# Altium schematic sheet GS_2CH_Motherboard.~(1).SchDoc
size A1; Dpartment: R&D; Date: 2024-10-27; DrawnBy: 杜龙彬; DocumentNumber: 2; Revision: V1.01; SheetNumber: 2; SheetTotal: 2; Model: 型号; Size: A1; Department: R&D
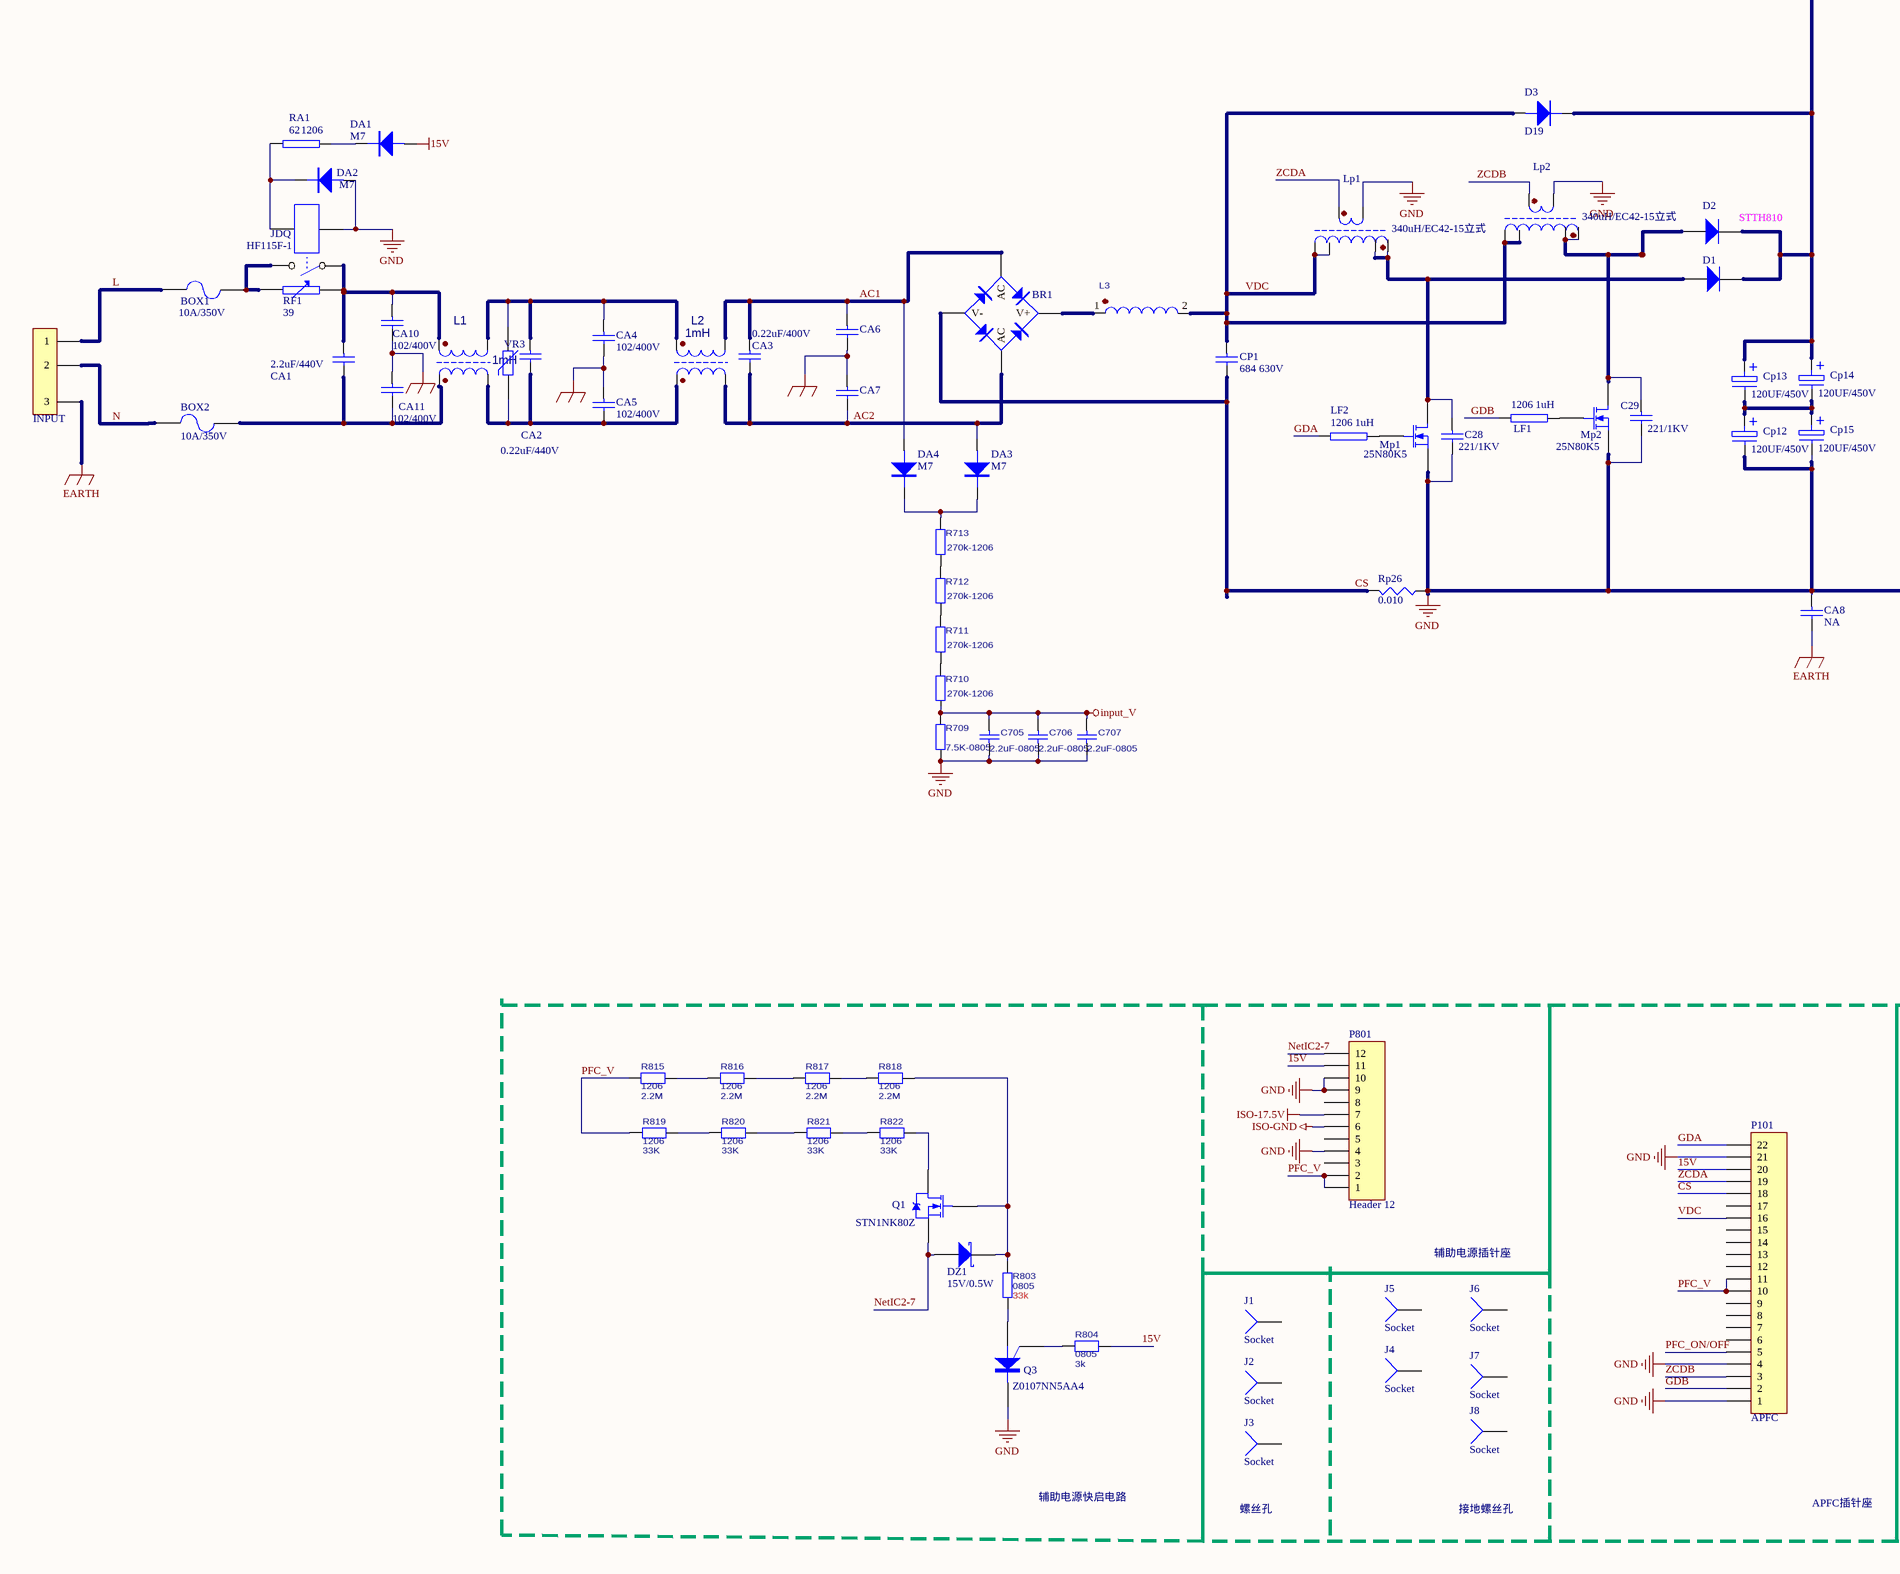
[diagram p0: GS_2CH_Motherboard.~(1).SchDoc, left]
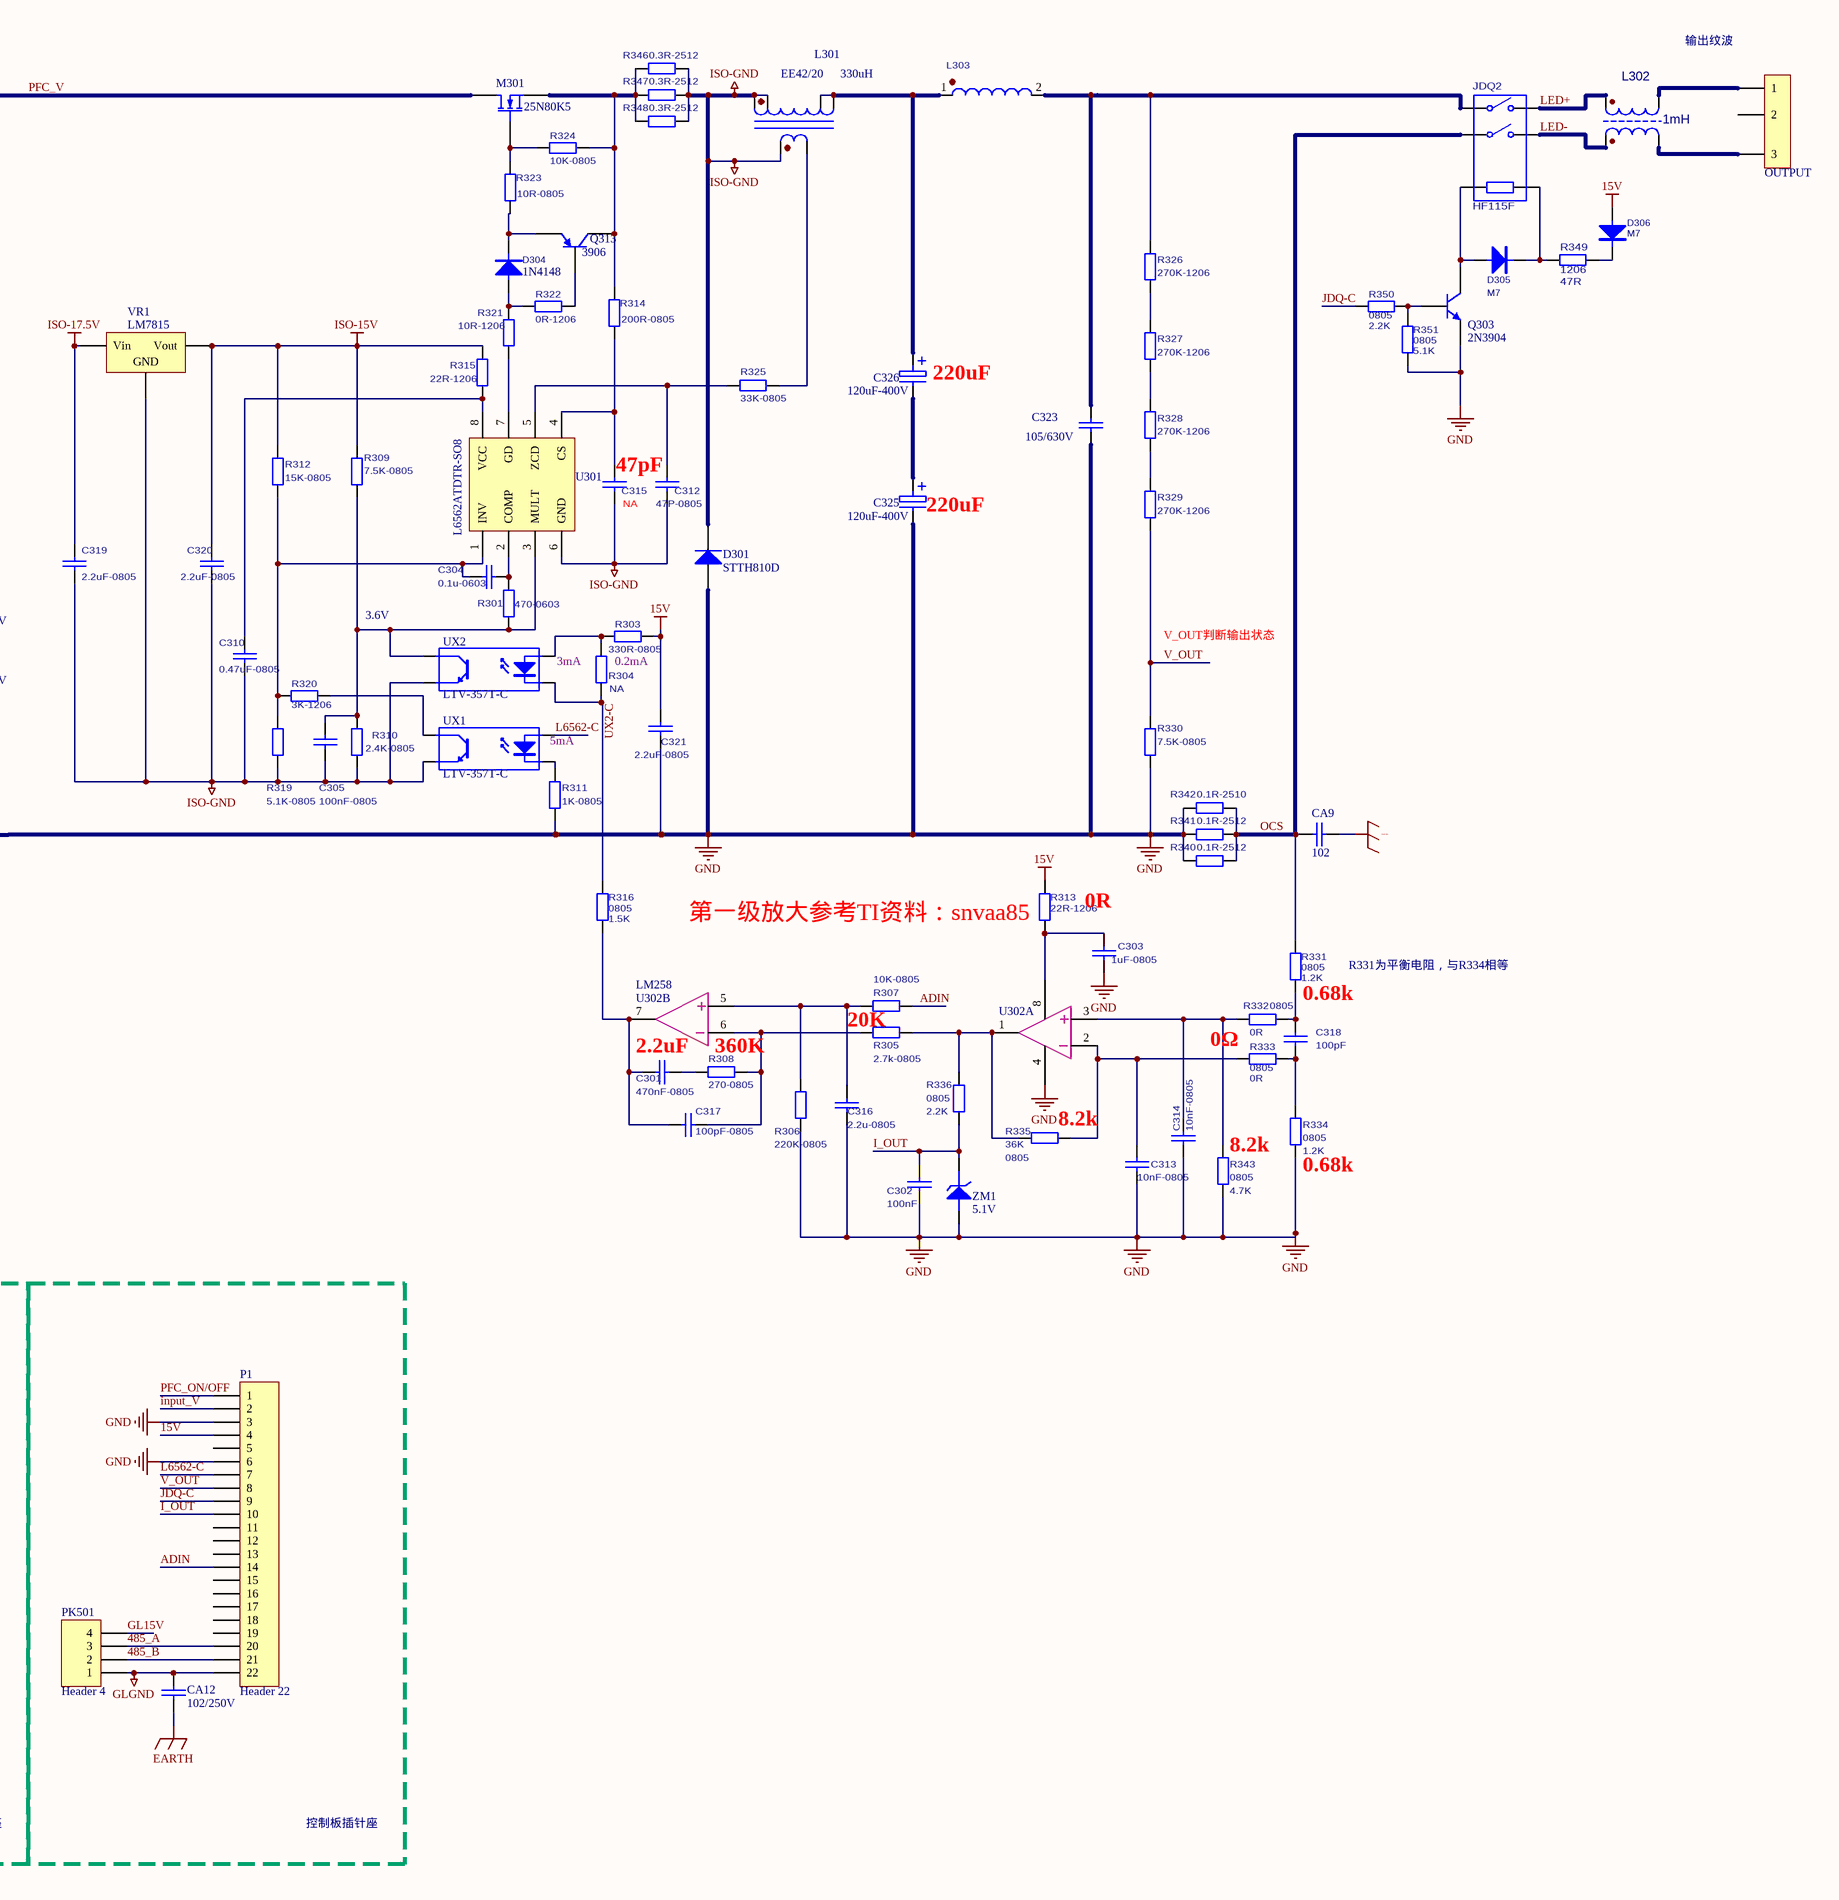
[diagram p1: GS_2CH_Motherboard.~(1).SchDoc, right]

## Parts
BOX1  10A/350V  [10A保险]
BOX2  10A/350V  [10A保险]
BR1  (no value)  [BRIDGE-TK]
C28  221/1KV  [Y2C]
C29  221/1KV  [Y2C]
C301  value 470nF-0805  [RW0805]
C302  value 100nF  [RW0805]  (hidden comment: 0805)
C303  value 1uF-0805  [RW0805]  (hidden comment: 301008)
C304  value 0.1u-0603  [RW0603]
C305  value 100nF-0805  [RW0805]  (hidden comment: 301008)
C310  value 0.47uF-0805  [RW0805]  (hidden comment: 301009)
C312  301001  [RW0805]  (value not drawn)
C313  value 10nF-0805  [RW0805]  (hidden comment: 301008)
C314  value 10nF-0805  [RW0805]  (hidden comment: 301008)
C315  (no value)  [RW0805]
C316  value 2.2u-0805  [RW0805]  (hidden comment: 301008)
C317  value 100pF-0805  [RW0805]  (hidden comment: 301008)
C318  value 100pF  [RW0805]  (hidden comment: 0805)
C319  value 2.2uF-0805  [RW0805]  (hidden comment: 301013)
C320  value 2.2uF-0805  [RW0805]  (hidden comment: 301013)
C321  value 2.2uF-0805  [RW0805]  (hidden comment: 301013)
C323  105/630V  [X2C-B 22-27]
C325  value 120uF-400V  [C250V/120uF]  (hidden comment: 302159)
C326  value 120uF-400V  [C250V/120uF]  (hidden comment: 302159)
C705  value 2.2uF-0805  [RW0805]  (hidden comment: 301008)
C706  value 2.2uF-0805  [RW0805]  (hidden comment: 301008)
C707  value 2.2uF-0805  [RW0805]  (hidden comment: 301008)
CA1  2.2uF/440V  [2.2uF/400V]
CA2  0.22uF/440V  [X2C-B 22-27]
CA3  0.22uF/400V  [X2C-B 22-27]
CA4  102/400V  [Y2C]
CA5  102/400V  [Y2C]
CA6  (no value)  [Y2C]
CA7  (no value)  [Y2C]
CA8  NA  [Y2C]
CA9  102  [Y2C]
CA10  102/400V  [Y2C]
CA11  102/400V  [Y2C]
CA12  102/250V  [Y2C]
CP1  684 630V  [2.2UF/630VRCD]
Cp12  120UF/450V  [C250V/120uF]
Cp13  120UF/450V  [C250V/120uF]
Cp14  120UF/450V  [C250V/120uF]
Cp15  120UF/450V  [C250V/120uF]
D1  STTH810  [U880]  (value not drawn)
D2  STTH810  [U880]
D3  D19  [D-SMC]
D301  value STTH810D  [U880]  (hidden comment: 308006)
D304  value 1N4148  [SOD-123]  (hidden comment: 307004)
D305  M7  [SMA]
D306  M7  [SMA]
DA1  M7  [M7]
DA2  M7  [M7]
DA3  M7  [M7]
DA4  M7  [M7]
DZ1  15V/0.5W  [SOD-123]
INPUT  INPUT  [INPUT-JST-6P]  (value not drawn)
J1  Socket  [螺丝孔]
J2  Socket  [螺丝孔]
J3  Socket  [螺丝孔]
J4  Socket  [接地标志]
J5  Socket  [接地标志]
J6  Socket  [接地标志]
J7  Socket  [接地标志]
J8  Socket  [接地标志]
JDQ  value HF115F-1  [RELAY-HF115F - 3]  (hidden comment: 12DC16A220VAC)
JDQ2  HF115F  [RELAY-HF115F]
L1  1mH  [L-EMC]
L2  1mH  [L-EMC]
L3  DM  [差模电感27*27*15，P=12]  (value not drawn)
L301  EE42/20  value 330uH  [EE42/20]
L302  1mH  [B-CM22X12]
L303  DM  [差模电感27*27*15，P=12]  (value not drawn)
LF1  1206  value 1uH  [RW1206]
LF2  1206  value 1uH  [RW1206]
Lp1  340uH/EC42-15立式  [W1U15-PF-5A]
Lp2  340uH/EC42-15立式  [W1U15-PF-5A]
M301  value 25N80K5  [TO220-3]  (hidden comment: 314012)
Mp1  25N80K5  [TO220-3]
Mp2  25N80K5  [TO220-3]
OUTPUT  INPUT  [INPUT-JST-6P]  (value not drawn)
P1  Header 22  [HDR1X22]
P101  APFC  [金手指-APFC]
P801  Header 12  [HDR1X12]
PK501  Header 4  [4针插座]
Q1  STN1NK80Z  [SOT-223-NPN]
Q3  Z0107NN5AA4  [SOT-223-NPN]
Q303  2N3904  [SOT-23-BEC]
Q313  value 3906  [SOT-23-BEC]  (hidden comment: 309005)
R301  value 470-0603  [RW0603]
R303  value 330R-0805  [RW0805]
R304  value NA  [RW0805]
R305  value 2.7k-0805  [RW0805]
R306  value 220K-0805  [RW0805]
R307  value 10K-0805  [RW0805]  (hidden comment: 303020)
R308  value 270-0805  [RW0805]  (hidden comment: 303046)
R309  value 7.5K-0805  [RW0805]
R310  value 2.4K-0805  [RW0805]
R311  value 1K-0805  [RW0805]
R312  value 15K-0805  [RW0805]  (hidden comment: 303053)
R313  value 22R-1206  [RW1206]  (hidden comment: 303074)
R314  value 200R-0805  [RW0805]
R315  value 22R-1206  [RW1206]  (hidden comment: 303074)
R316  0805  value 1.5K  [RW0805]
R319  value 5.1K-0805  [RW0805]
R320  value 3K-1206  [RW1206]
R321  value 10R-1206  [RW1206]  (hidden comment: 303075)
R322  value 0R-1206  [RW1206]
R323  value 10R-0805  [RW0805]  (hidden comment: 303073)
R324  value 10K-0805  [RW0805]  (hidden comment: 303043)
R325  value 33K-0805  [RW0805]  (hidden comment: 303055)
R326  value 270K-1206  [RW1206]  (hidden comment: 303094)
R327  value 270K-1206  [RW1206]  (hidden comment: 303094)
R328  value 270K-1206  [RW1206]  (hidden comment: 303094)
R329  value 270K-1206  [RW1206]  (hidden comment: 303094)
R330  value 7.5K-0805  [RW0805]  (hidden comment: 303033)
R331  0805  value 1.2K  [RW0805]
R332  0805  value 0R  [RW0805]
R333  0805  value 0R  [RW0805]
R334  0805  value 1.2K  [RW0805]
R335  0805  value 36K  [RW0805]
R336  0805  value 2.2K  [RW0805]
R340  value 0.1R-2512  [RW2512]
R341  value 0.1R-2512  [RW2512]
R342  value 0.1R-2510  [RW2512]
R343  0805  value 4.7K  [RW0805]
R346  value 0.3R-2512  [RW2512]
R347  value 0.3R-2512  [RW2512]
R348  value 0.3R-2512  [RW2512]
R349  1206  value 47R  [RW1206]
R350  0805  value 2.2K  [RW0805]
R351  0805  value 5.1K  [RW0805]
R709  value 7.5K-0805  [RW0805]  (hidden comment: 303046)
R710  value 270k-1206  [RW1206]  (hidden comment: 303098)
R711  value 270k-1206  [RW1206]  (hidden comment: 303098)
R712  value 270k-1206  [RW1206]  (hidden comment: 303098)
R713  value 270k-1206  [RW1206]  (hidden comment: 303098)
R803  0805  value 33k  [RW0805]
R804  0805  value 3k  [RW0805]
R815  1206  value 2.2M  [RW1206]
R816  1206  value 2.2M  [RW1206]
R817  1206  value 2.2M  [RW1206]
R818  1206  value 2.2M  [RW1206]
R819  1206  value 33K  [RW1206]
R820  1206  value 33K  [RW1206]
R821  1206  value 33K  [RW1206]
R822  1206  value 33K  [RW1206]
RA1  62  [RW1206]
RF1  39  [热敏]
Rp26  0.010  [康铜丝]
U301  value L6562ATDTR-SO8  [SO-8]  (hidden comment: 311046)
U302  311026  [SOP-8]  (value not drawn)  (parts A,B of 2)
UX1  value LTV-357T-C  [LTV]  (hidden comment: 317001)
UX2  value LTV-357T-C  [LTV]  (hidden comment: 317001)
VR1  LM7815  [78M05]
VR3  20D781  [YAMIN-7.62]  (value not drawn)
ZM1  5.1V  [二极管]

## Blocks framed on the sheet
辅助电源插针座: P801
APFC插针座: P101
控制板插针座: CA12 P1 PK501

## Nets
15V: C321.1 D306.A DA1.1(A) P1.4 P101.20 P801.11 R303.1 R313.2 R804.1
EARTH: CA4.2 CA5.1 CA6.2 CA7.1 CA8.2 CA9.2 CA10.2 CA11.1 CA12.2 INPUT.3
GLGND: CA12.1 P1.22 PK501.1
GND: C28.2 C29.2 C302.2 C303.2 C313.2 C314.2 C316.2 C321.2 C323.2 C325.2 C705.1 C706.1 C707.1 CA8.1 Cp12.2 Cp15.2 D301.1 DA2.1(A) JDQ.3 Lp1.4 Lp2.4 Mp1.3 Mp2.3 P1.3 P1.6 P101.1 P101.4 P101.21 P801.4 P801.9 P801.10 Q3.B(K) Q303.E R306.1 R311.1 R330.1 R334.2 R340.1 R341.1 R342.1 R343.2 R351.1 R709.1 Rp26.1 U302.4(U-) ZM1.1(A)
input_V: C705.2 C706.2 C707.2 P1.2 R709.2 R710.2
ISO-15V: C320.1 R309.2 R312.1 R315.2 VR1.3(Vout)
ISO-17.5V: C319.1 P801.7 VR1.1(Vin)
ISO-GND: C305.1 C310.2 C312.2 C315.2 C319.2 C320.2 D301.2 L301.6 L301.7 L301.8 P801.6 R310.1 R319.1 R346.2 R347.2 R348.2 U301.6(GND) UX1.3(E) UX2.3(E) VR1.2(GND)
485_A: P1.20 PK501.3
485_B: P1.21 PK501.2
AC1: BR1.3(AC) CA3.1 CA6.1 DA4.1(A) L2.4
AC2: BR1.2(AC) CA3.2 CA7.2 DA3.1(A) L2.2
ADIN: P1.14 R307.2
CS: BR1.1(V-) CP1.2 P101.18 Rp26.2
GDA: LF2.1 P101.22
GDB: LF1.1 P101.2
GL15V: PK501.4
I_OUT: C302.1 P1.10 R336.2 ZM1.2(K)
JDQ-C: P1.9 R350.1
L: BOX1.1 INPUT.1
L6562-C: P1.7 UX1.1(A)
LED+: JDQ2.3 L302.3
LED-: JDQ2.4 L302.1
N: BOX2.2 INPUT.2
NetIC2-7: DZ1.1(A) P801.12 Q1.E
OCS: CA9.1 JDQ2.6 R331.1 R340.2 R341.2 R342.2
PFC_ON/OFF: P1.1 P101.5
PFC_V: Cp13.1 Cp14.1 D1.2(K) D2.2 D3.2(K) M301.2 P101.10 P101.11 P801.1 P801.2 R815.1 R819.1
UX2-C: R304.2 R316.1 UX2.2(K)
V_OUT: P1.8 R329.2 R330.2
VDC: CP1.1 D3.1(A) L3.2 Lp1.9 Lp1.10 Lp2.9 Lp2.10 P101.16
ZCDA: Lp1.5 P101.19
ZCDB: Lp2.5 P101.3
NetBOX1_2: BOX1.2 JDQ.1 RF1.1
NetBOX2_1: BOX2.1 CA1.2 CA11.2 L1.1
NetBR1_4: BR1.4(V+) L3.1
NetC28_1: C28.1 D1.1(A) Lp1.12 Lp1.13 Mp1.2
NetC29_1: C29.1 D2.1 Lp2.12 Lp2.13 Mp2.2
NetC301_1: C301.1 R308.1
NetC301_2: C301.2 C317.2 R316.2 U302.7
NetC303_1: C303.1 R313.1 U302.8(U+)
NetC304_1: C304.1 R301.1 U301.2(COMP)
NetC304_2: C304.2 R312.2 R319.2 R320.2 U301.1(INV)
NetC305_2: C305.2 R301.2 R309.1 R310.2 U301.3(MULT) UX2.4(C)
NetC310_1: C310.1 R315.1 U301.8(VCC)
NetC312_1: C312.1 R325.1 U301.5(ZCD)
NetC313_1: C313.1 R333.1 R335.1 U302.2
NetC314_1: C314.1 R332.2 R343.1 U302.3
NetC315_1: C315.1 R314.1 U301.4(CS)
NetC316_1: C316.1 R306.2 R307.1 U302.5
NetC317_1: C317.1 R305.1 R308.2 U302.6
NetC318_1: C318.1 R331.2 R332.1
NetC318_2: C318.2 R333.2 R334.1
NetC323_1: C323.1 JDQ2.5 L303.2 R326.1
NetC325_1: C325.1 C326.2
NetC326_1: C326.1 L301.10 L301.11 L303.1
NetCA1_1: CA1.1 CA10.1 JDQ.2 L1.3 RF1.2
NetCA2_1: CA2.1 CA4.1 L1.4 L2.3 VR3.1
NetCA2_2: CA2.2 CA5.2 L1.2 L2.1 VR3.2
NetCp12_1: Cp12.1 Cp13.2 Cp14.2 Cp15.1
NetD304_A: D304.A R321.1 R322.1
NetD304_K: D304.K Q313.E R323.1
NetD305_A: D305.A JDQ2.1 Q303.C
NetD305_K: D305.K JDQ2.2 R349.2
NetD306_K: D306.K R349.1
NetDA1_2: DA1.2(K) RA1.2
NetDA2_2: DA2.2(K) JDQ.4 RA1.1
NetDA3_2: DA3.2(K) DA4.2(K) R713.1
NetDZ1_2: DZ1.2(K) Q1.B R803.1 R818.2
NetL301_4: L301.4 R325.2
NetL302_2: L302.2 OUTPUT.3
NetL302_4: L302.4 OUTPUT.1
NetLF1_2: LF1.2 Mp2.1
NetLF2_2: LF2.2 Mp1.1
NetM301_1: M301.1 R323.2 R324.2
NetM301_3: M301.3 Q313.C R314.2 R324.1 R346.1 R347.1 R348.1
NetQ1_C: Q1.C R822.2
NetQ3_C: Q3.C(A) R803.2
NetQ3_E: Q3.E(G) R804.2
NetQ303_B: Q303.B R350.2 R351.2
NetQ313_B: Q313.B R322.2
NetR303_2: R303.2 R304.1 UX2.1(A)
NetR305_2: R305.2 R335.2 R336.1 U302.1
NetR311_2: R311.2 UX1.2(K)
NetR320_1: R320.1 UX1.4(C)
NetR321_2: R321.2 U301.7(GD)
NetR326_2: R326.2 R327.1
NetR327_2: R327.2 R328.1
NetR328_2: R328.2 R329.1
NetR710_1: R710.1 R711.2
NetR711_1: R711.1 R712.2
NetR712_1: R712.1 R713.2
NetR815_2: R815.2 R816.1
NetR816_2: R816.2 R817.1
NetR817_2: R817.2 R818.1
NetR819_2: R819.2 R820.1
NetR820_2: R820.2 R821.1
NetR821_2: R821.2 R822.1

Not connected (* = marked no-connect by the designer): J1 1; J2 1; J3 1; J4 1; J5 1; J6 1; J7 1; J8 1; OUTPUT 2; P1 5 11 12 13 15 16 17 18 19; P101 6 7 8 9 12 13 14 15 17; P801 3 5 8

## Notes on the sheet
- 输出纹波
- (near RA1) 1206
- (near C326) 220uF
- (near C315) 47pF
- (near C325) 220uF
- 3.6V
- V_OUT判断输出状态
- (near UX2) 3mA
- 0.2mA
- (near UX1) 5mA
- 0R
- 第一级放大参考TI资料：snvaa85
- R331为平衡电阻，与R334相等
- 20K
- 0Ω
- (near R331) 0.68k
- (near U302) 2.2uF
- 360K
- (near R335) 8.2k
- (near R343) 8.2k
- (near R334) 0.68k
- 辅助电源快启电路
- 螺丝孔
- 接地螺丝孔

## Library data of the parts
BOX1 BOX2 = FUSE2: Fuse
BR1 = BRIEGR
C28 C29 C302 C318 = C
C301 C303-C305 C313 C314 C316 C317 = CAP: 贴片电容
C310 C312 C315 C319-C321 = C: 贴片电容
C323 CA1-CA12 CP1 = CAP: Capacitor
C325 C326 = CAP ELECTROLYTIC: 直插电容
C705-C707 = Cap: 贴片电容
Cp12-Cp15 = CAP ELECTROLYTIC
D1 D2 = Diode 1N914: High Conductance Fast Diode; pin to pad: 1>3 2>1
D3 DA1-DA4 = DIO: pin to pad: 1>A 2>K
D301 = Diode 1N914: 直插二极管; pin to pad: 1>3 2>1
D304 = DIO: 贴片二极管
D305 D306 = DIO
DZ1 = D Schottky: Schottky Diode; pin to pad: 1>A 2>K
INPUT OUTPUT = CON6: Connector
JDQ = RELAY-SPST
JDQ2 = Relay - 两组常开: Dual-Pole Single-Throw Relay
L1 L2 L302 = L1
L3 L303 = 差模电感
L301 = inductance2
LF1 LF2 RA1 = RES
Lp1 Lp2 = L-PFC-33262
M301 = MOSFET-N: TO220mos管; pin to pad: 1>G 2>D 3>S; PackageDocument: 1995/1996
Mp1 Mp2 = MOSFET-N: N-Channel MOSFET; pin to pad: 1>G 2>D 3>S; PackageDocument: 1995/1996
P1 P101 = Header 22: Header, 22-Pin
P801 = Header 12: Header, 12-Pin
PK501 = Header 4: Header, 4-Pin
Q1 = NMOS-2: N-Channel Power MOSFET; Note: Pin 2 is electrically connected to pin 4.
Q3 = PUT: Programmable Unijunction Transistor
Q303 = NPN: NPN Bipolar Transistor
Q313 = PNP: 贴片三极管
R301 R303-R315 R319-R330 R340-R342 R346-R348 R709-R713 = Res2: 贴片电阻
R316 R331-R336 R343 R349-R351 R803 R804 R815-R822 = Res2: Resistor
RF1 = RES4
Rp26 = RES1
U301 = L6562: 贴片集成电路
U302 = LM393: 贴片集成电路
UX1 UX2 = Optoisolator1: 贴片光耦
VR1 = Volt Reg: Voltage Regulator
VR3 = VARISTOR
ZM1 = 稳压管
